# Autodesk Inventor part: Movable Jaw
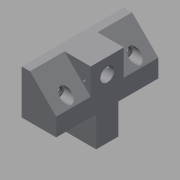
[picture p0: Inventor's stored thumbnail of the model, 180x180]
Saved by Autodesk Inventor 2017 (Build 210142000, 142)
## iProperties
Shininess: 77.0
Length Units: 11269
Angle Units: 11279
Time Units: 11290
Mass Units: 11283
Length Display Precision: 3
Angle Display Precision: 2
Created: 2002-02
Part Number: Movable Jaw
Document SubType Name: Modeling
Designer: ***
Density: 1 g/cm^3
Material: Generic
Mass: 56.5588 g
Surface Area: 124.299 cm^2
Volume: 56.5588 cm^3
Appearance: Default
Density: 0.0
Volumn: 0.0
Area: 0.0
PropertySet Name: Model Information
Control State: 0
Master: False
Checked Out: False
Author: ***
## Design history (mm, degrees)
sketch "Sketch2"
  geometry: L1 (2.39, 41.509)-(2.39, 9.509); L2 (2.39, 9.509)-(-22.61, 9.509); L3 (-22.61, 9.509)-(-22.61, 22.509); L4 (-22.61, 22.509)-(-3.61, 41.509); L5 (-3.61, 41.509)-(2.39, 41.509)
  constraints: 10 end point, 2 parallel, 1 perpendicular, 1 vertical
  dimensions: "d0" = 25 distance of L1.end L2.end; "d2" = 13 distance of L2.end L3.end; "d3" = 32 distance between parallel lines of L5 L2; "d4" = 6 distance of L4.end L1.start
extrude "Extrusion1" new body sketch "Sketch2" stored distance "d5" = 74; taper "d6" = 0 deg
sketch "Sketch3"
  geometry: L1 (-19, 25)-(11, 25); L2 (11, 25)-(11, 49); L3 (11, 49)-(-19, 49); L4 (-19, 49)-(-19, 25); L5 (0, 0)-(13, 0) reference; L6 (-19, 74)-(-19, 0) reference; L7 (11.924, 29)-(35, 29); L8 (35, 29)-(35, 45); L9 (35, 45)-(11.924, 45); L10 (11.924, 45)-(11.924, 29); L11 (13, 74)-(13, 0) reference
  constraints: 16 end point, 4 parallel, 2 horizontal, 2 perpendicular, 1 collinear
  dimensions: "d7" = 24 distance of L3.end L1.start; "d8" = 30 distance of L1.start L1.end; "d9" = 25 distance between parallel lines of L5 L1; "d10" = 16 distance of L7.end L8.end; "d11" = 4 distance between parallel lines of L3 L9; "d12" = 22 distance between parallel lines of L11 L8
extrude "Extrusion2" join sketch "Sketch3" distance "d13" = 25; taper "d14" = 0 deg
sketch "Sketch4"
  geometry: L1 (-19, -25)-(-19, -49) reference; L2 (-19, -49)-(0, -49) reference; 1 further point
  dimensions: "d15" = 11 distance from line of L1 point (-8, -37); "d16" = 12 distance from line of L2 point (-8, -37)
hole "Hole1" sketch "Sketch4" at (-8, -37) diameter "d17" = 10; stored, may be unused: countersink angle "d21" = 82 deg, drill point angle "d23" = 0 deg; dims "d18" = 6, "d19" = 4, "d20" = 2, "d22" = 13
sketch "Sketch5"
  geometry: L1 (-19, -49)-(-19, -74) reference; L2 (0, -74)-(13, -74) reference; 1 further point
  dimensions: "d24" = 14 distance from line of L1 point (-5, -62); "d25" = 12 distance from line of L2 point (-5, -62)
hole "Hole2" sketch "Sketch5" at (-5, -62) diameter "d26" = 4.917; stored, may be unused: countersink angle "d30" = 82 deg, drill point angle "d32" = 0 deg; dims "d27" = 12, "d28" = 8, "d29" = 10, "d31" = 17.1
mirror "Mirror1"
sketch "Sketch6"
  geometry: L1 (0, 19)-(0, 0) reference; 1 further point
  dimensions: "d33" = 5 distance from line of L1 point (-5, 8); "d34" = 11 vertical distance of L1.start point (-5, 8)
hole "Hole3" sketch "Sketch6" at (-5, 8) diameter "d35" = 2; stored, may be unused: countersink angle "d39" = 82 deg, drill point angle "d41" = 0 deg; dims "d36" = 6, "d37" = 8, "d38" = 10, "d40" = 13
body "Solid1"
